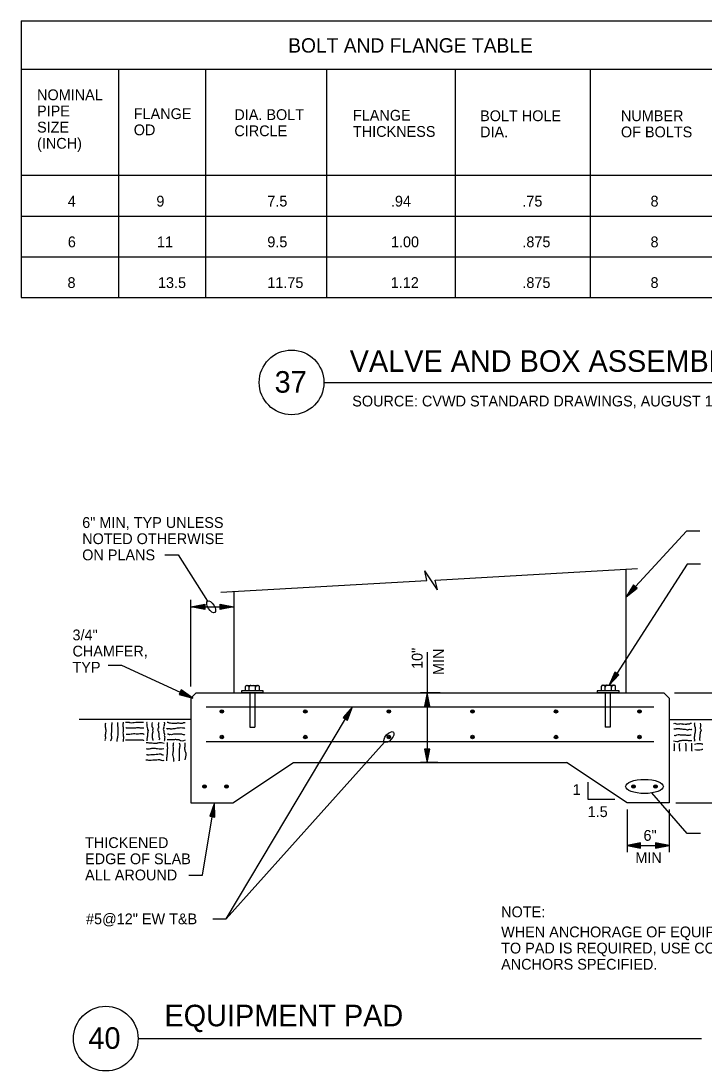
# Model space of a CAD drawing. Extents: x -121933 to -117742, y -103160 to -100084.
# Drawn here: x -121933 to -121553, y -102523 to -101938 of the extents above; entities that cross this region are included whole.
import ezdxf

# ---------------------------------------------------------------- set-up
doc = ezdxf.new("R2010")
doc.units = 0
for name, color, linetype in [('G-MARK', 7, 'Continuous'), ('G-TEXT', 7, 'Continuous'), ('Misc CnstDet(22)', 7, 'Continuous')]:
    doc.layers.add(name, color=color, linetype=linetype)

msp = doc.modelspace()

# ---------------------------------------------------------------- linework, layer by layer
at = {"layer": 'G-MARK'}
for p, q in [((-121814.85, -102255.67), (-121814.85, -102312.1)), ((-121838.79, -102308.56), (-121838.79, -102260.32)), ((-121838.79, -102264.16), (-121814.85, -102264.16)), ((-121707.41, -102289.5), (-121707.41, -102312.1)), ((-121707.41, -102312.1), (-121707.41, -102350.84)), ((-121569.78, -102312.1), (-121533.12, -102312.1)), ((-121569.05, -102373.35), (-121534.56, -102373.35)), ((-121596.02, -102397.06), (-121572.78, -102397.06))]:
    msp.add_line(p, q, dxfattribs=at)
for points in [[(-121555.66, -102222.01), (-121563.1, -102222.01), (-121591.46, -102252.81)], [(-121853.39, -102235.19), (-121845.95, -102235.19), (-121829.53, -102261.05)], [(-121555.27, -102240.38), (-121562.71, -102240.38), (-121601.87, -102301.24)], [(-121884.84, -102296.67), (-121877.4, -102296.67), (-121844.85, -102311.7)], [(-121826.61, -102437.78), (-121819.17, -102437.78), (-121752.89, -102326.51)], [(-121826.61, -102437.78), (-121819.17, -102437.78), (-121731.12, -102339.42)], [(-121603.03, -102371.42), (-121617.7, -102371.42), (-121617.7, -102361.72)], [(-121555.27, -102390.27), (-121562.71, -102390.27), (-121582.26, -102367.75)], [(-121839.9, -102413.63), (-121832.46, -102413.63), (-121826.94, -102380.99)]]:
    msp.add_lwpolyline(points, dxfattribs=at)
msp.add_ellipse((-121586.43, -102364.15), major_axis=(-10.49, 0), ratio=0.373805, dxfattribs=at)
at = {"layer": 'G-TEXT'}
for points in [[(-121590.45, -102253.74), (-121592.46, -102251.89), (-121596.71, -102258.52), (-121590.45, -102253.74), (-121591.71, -102253.09), (-121592.36, -102252.33), (-121595.53, -102257.33), (-121590.81, -102253.75), (-121591.88, -102253.27), (-121592.33, -102252.85), (-121594.56, -102256.28), (-121591.42, -102253.87), (-121592.32, -102253.11), (-121593.64, -102255.19), (-121591.86, -102253.8), (-121592.39, -102253.56), (-121592.8, -102254.27), (-121591.46, -102252.81)], [(-121831.1, -102262.74), (-121831.1, -102265.59), (-121838.79, -102264.16), (-121831.1, -102262.74), (-121831.48, -102264.16), (-121831.35, -102265.16), (-121837.06, -102264.1), (-121831.35, -102263.05), (-121831.72, -102264.16), (-121831.72, -102264.78), (-121835.69, -102264.1), (-121831.85, -102263.42), (-121831.91, -102264.6), (-121834.27, -102264.16), (-121832.1, -102263.79), (-121832.28, -102264.35), (-121833.03, -102264.16), (-121831.1, -102264.16)], [(-121822.54, -102265.59), (-121822.54, -102262.74), (-121814.85, -102264.16), (-121822.54, -102265.59), (-121822.17, -102264.16), (-121822.3, -102263.17), (-121816.59, -102264.23), (-121822.3, -102265.28), (-121821.92, -102264.16), (-121821.92, -102263.54), (-121817.96, -102264.23), (-121821.8, -102264.91), (-121821.74, -102263.73), (-121819.38, -102264.16), (-121821.55, -102264.54), (-121821.37, -102263.98), (-121820.62, -102264.16), (-121822.54, -102264.16)], [(-121600.72, -102301.98), (-121603.01, -102300.5), (-121606.06, -102307.76), (-121600.72, -102301.98), (-121602.07, -102301.55), (-121602.84, -102300.91), (-121605.1, -102306.38), (-121601.06, -102302.05), (-121602.2, -102301.76), (-121602.72, -102301.42), (-121604.33, -102305.18), (-121601.64, -102302.27), (-121602.67, -102301.68), (-121603.61, -102303.95), (-121602.09, -102302.27), (-121602.66, -102302.13), (-121602.94, -102302.91), (-121601.87, -102301.24)], [(-121844.28, -102310.46), (-121845.42, -102312.94), (-121837.81, -102314.95), (-121844.28, -102310.46), (-121844.51, -102311.86), (-121845.04, -102312.71), (-121839.31, -102314.2), (-121844.16, -102310.79), (-121844.29, -102311.96), (-121844.55, -102312.53), (-121840.6, -102313.6), (-121843.86, -102311.34), (-121844.3, -102312.44), (-121841.92, -102313.06), (-121843.79, -102311.78), (-121843.86, -102312.37), (-121843.05, -102312.54), (-121844.85, -102311.71)], [(-121708.89, -102319.54), (-121705.92, -102319.54), (-121707.41, -102312.1), (-121708.89, -102319.54), (-121707.41, -102319.18), (-121706.32, -102319.3), (-121707.47, -102313.71), (-121708.62, -102319.3), (-121707.41, -102318.94), (-121706.73, -102318.94), (-121707.47, -102315.07), (-121708.22, -102318.82), (-121706.93, -102318.77), (-121707.41, -102316.44), (-121707.81, -102318.59), (-121707.2, -102318.41), (-121707.41, -102317.63), (-121707.41, -102319.54)], [(-121754.06, -102325.81), (-121751.71, -102327.2), (-121748.92, -102319.85), (-121754.06, -102325.81), (-121752.69, -102326.19), (-121751.91, -102326.8), (-121749.83, -102321.25), (-121753.72, -102325.72), (-121752.57, -102325.97), (-121752.04, -102326.29), (-121750.56, -102322.48), (-121753.14, -102325.49), (-121752.1, -102326.04), (-121751.23, -102323.74), (-121752.7, -102325.46), (-121752.12, -102325.59), (-121751.87, -102324.8), (-121752.89, -102326.51)], [(-121705.92, -102343.4), (-121708.89, -102343.4), (-121707.41, -102350.84), (-121705.92, -102343.4), (-121707.41, -102343.76), (-121708.49, -102343.64), (-121707.34, -102349.23), (-121706.19, -102343.64), (-121707.41, -102344), (-121708.08, -102344), (-121707.34, -102347.86), (-121706.59, -102344.11), (-121707.88, -102344.17), (-121707.41, -102346.5), (-121707, -102344.35), (-121707.61, -102344.53), (-121707.41, -102345.31), (-121707.41, -102343.4)], [(-121828.28, -102380.76), (-121825.59, -102381.22), (-121825.65, -102373.35), (-121828.28, -102380.76), (-121826.88, -102380.62), (-121825.92, -102380.91), (-121825.98, -102374.99), (-121828, -102380.56), (-121826.83, -102380.38), (-121826.22, -102380.48), (-121826.22, -102376.39), (-121827.55, -102380.13), (-121826.38, -102380.27), (-121826.4, -102377.81), (-121827.14, -102379.95), (-121826.56, -102379.86), (-121826.61, -102379.03), (-121826.94, -102380.99)], [(-121588.59, -102398.56), (-121588.59, -102395.58), (-121596.03, -102397.07), (-121588.59, -102398.56), (-121588.94, -102397.07), (-121588.82, -102395.99), (-121594.42, -102397.13), (-121588.82, -102398.28), (-121589.18, -102397.07), (-121589.18, -102396.39), (-121593.05, -102397.13), (-121589.3, -102397.88), (-121589.36, -102396.59), (-121591.68, -102397.07), (-121589.54, -102397.47), (-121589.72, -102396.86), (-121590.49, -102397.07), (-121588.59, -102397.07)], [(-121580.22, -102395.58), (-121580.22, -102398.56), (-121572.78, -102397.07), (-121580.22, -102395.58), (-121579.87, -102397.07), (-121579.98, -102398.15), (-121574.39, -102397), (-121579.98, -102395.85), (-121579.63, -102397.07), (-121579.63, -102397.74), (-121575.76, -102397), (-121579.51, -102396.26), (-121579.45, -102397.54), (-121577.13, -102397.07), (-121579.27, -102396.66), (-121579.09, -102397.27), (-121578.32, -102397.07), (-121580.22, -102397.07)]]:
    msp.add_lwpolyline(points, dxfattribs=at)
for centre, major_axis in [((-121827.56, -102264.17), (1.99, -3.14)), ((-121728.65, -102336.68), (2.48, 2.77))]:
    msp.add_ellipse(centre, major_axis=major_axis, ratio=0.483333, dxfattribs=at)
at = {"layer": 'Misc CnstDet(22)'}
for p, q in [((-121933.35, -101938.08), (-121933.35, -102091.98)), ((-121933.35, -101938.08), (-121476.56, -101938.08)), ((-121933.35, -101964.93), (-121476.56, -101964.93)), ((-121879.09, -101964.93), (-121879.09, -102091.98)), ((-121830.78, -101964.93), (-121830.78, -102091.98)), ((-121763.4, -101964.93), (-121763.4, -102091.98)), ((-121691.84, -101964.93), (-121691.84, -102091.98)), ((-121616.7, -101964.93), (-121616.7, -102091.98)), ((-121933.35, -102023.98), (-121476.56, -102023.98)), ((-121933.35, -102046.65), (-121476.56, -102046.65)), ((-121933.35, -102069.32), (-121476.56, -102069.32)), ((-121933.35, -102091.98), (-121476.56, -102091.98)), ((-121764.82, -102139.26), (-121443.02, -102139.26)), ((-121707.58, -102249.59), (-121708.7, -102244.2)), ((-121701.69, -102254.74), (-121708.7, -102244.2)), ((-121702.99, -102249.28), (-121590.32, -102242.89)), ((-121596.71, -102312.1), (-121596.71, -102243.27)), ((-121822.11, -102256.04), (-121707.58, -102249.59)), ((-121707.58, -102249.59), (-121707.58, -102249.59)), ((-121701.69, -102254.74), (-121702.99, -102249.34)), ((-121702.99, -102249.34), (-121702.99, -102249.34)), ((-121814.85, -102264.16), (-121814.85, -102264.16)), ((-121808.41, -102310.98), (-121808.41, -102308.5)), ((-121807.79, -102307.88), (-121801.46, -102307.88)), ((-121806.42, -102310.98), (-121806.42, -102308.87)), ((-121802.83, -102310.98), (-121802.83, -102308.87)), ((-121800.72, -102310.98), (-121800.72, -102308.5)), ((-121610.29, -102310.86), (-121610.29, -102308.38)), ((-121609.67, -102307.76), (-121603.34, -102307.76)), ((-121608.3, -102310.86), (-121608.3, -102308.75)), ((-121604.71, -102310.86), (-121604.71, -102308.75)), ((-121602.6, -102310.86), (-121602.6, -102308.38)), ((-121838.79, -102315), (-121835.89, -102312.1)), ((-121838.79, -102315), (-121838.79, -102373.35)), ((-121835.89, -102312.1), (-121575.68, -102312.1)), ((-121806.08, -102311.91), (-121806.08, -102331.1)), ((-121803.17, -102311.91), (-121803.17, -102331.1)), ((-121700.05, -102312.1), (-121711.13, -102312.1)), ((-121608.4, -102311.91), (-121608.4, -102331.1)), ((-121605.49, -102311.91), (-121605.49, -102331.1)), ((-121575.68, -102312.1), (-121572.77, -102315)), ((-121572.77, -102315), (-121572.77, -102373.35)), ((-121830.36, -102319.85), (-121581.21, -102319.85)), ((-121838.79, -102326.86), (-121900.99, -102326.86)), ((-121572.77, -102326.86), (-121482.92, -102326.86)), ((-121806.08, -102331.1), (-121803.17, -102331.1)), ((-121605.49, -102331.1), (-121608.4, -102331.1)), ((-121830.36, -102339.22), (-121581.21, -102339.22)), ((-121815.55, -102373.35), (-121781.79, -102350.84)), ((-121781.79, -102350.84), (-121629.78, -102350.84)), ((-121701.44, -102350.84), (-121711.13, -102350.84)), ((-121596.02, -102373.35), (-121629.78, -102350.84)), ((-121838.79, -102373.35), (-121815.55, -102373.35)), ((-121572.77, -102373.35), (-121596.02, -102373.35)), ((-121596.02, -102377.07), (-121596.02, -102400.79)), ((-121572.78, -102377.07), (-121572.78, -102400.79)), ((-121868.18, -102504.54), (-121554.73, -102504.54))]:
    msp.add_line(p, q, dxfattribs=at)
for points in [[(-121810.7, -102311.91), (-121798.55, -102311.91), (-121798.55, -102310.98), (-121810.7, -102310.98)], [(-121612.71, -102311.91), (-121600.55, -102311.91), (-121600.55, -102310.98), (-121612.71, -102310.98)]]:
    msp.add_lwpolyline(points, close=True, dxfattribs=at)
for centre, radius in [((-121782.82, -102139.26), 18), ((-121821.64, -102322.39), 0.969), ((-121821.64, -102322.39), 0.581), ((-121821.64, -102322.39), 0.176), ((-121775.15, -102322.39), 0.969), ((-121775.15, -102322.39), 0.581), ((-121775.15, -102322.39), 0.176), ((-121728.66, -102322.39), 0.969), ((-121728.66, -102322.39), 0.581), ((-121728.66, -102322.39), 0.176), ((-121682.17, -102322.39), 0.969), ((-121682.17, -102322.39), 0.581), ((-121682.17, -102322.39), 0.176), ((-121635.68, -102322.39), 0.969), ((-121635.68, -102322.39), 0.581), ((-121635.68, -102322.39), 0.176), ((-121589.18, -102322.39), 0.969), ((-121589.18, -102322.39), 0.581), ((-121589.18, -102322.39), 0.176), ((-121821.64, -102336.67), 0.969), ((-121821.64, -102336.67), 0.581), ((-121821.64, -102336.67), 0.176), ((-121775.15, -102336.67), 0.969), ((-121775.15, -102336.67), 0.581), ((-121775.15, -102336.67), 0.176), ((-121728.66, -102336.67), 0.969), ((-121728.66, -102336.67), 0.581), ((-121728.66, -102336.67), 0.176), ((-121682.17, -102336.67), 0.969), ((-121682.17, -102336.67), 0.581), ((-121682.17, -102336.67), 0.176), ((-121635.68, -102336.67), 0.969), ((-121635.68, -102336.67), 0.581), ((-121635.68, -102336.67), 0.176), ((-121589.18, -102336.67), 0.969), ((-121589.18, -102336.67), 0.581), ((-121589.18, -102336.67), 0.176), ((-121831.25, -102364.18), 0.969), ((-121831.25, -102364.18), 0.581), ((-121831.25, -102364.18), 0.176), ((-121819.02, -102364.18), 0.969), ((-121819.02, -102364.18), 0.581), ((-121819.02, -102364.18), 0.176), ((-121592.54, -102364.18), 0.969), ((-121592.54, -102364.18), 0.581), ((-121592.54, -102364.18), 0.176), ((-121580.32, -102364.18), 0.969), ((-121580.32, -102364.18), 0.581), ((-121580.32, -102364.18), 0.176), ((-121886.18, -102504.54), 18)]:
    msp.add_circle(centre, radius, dxfattribs=at)
for centre, radius, start, end in [((-121807.81, -102308.56), 0.674, 90.00002, 180.00002), ((-121807.41, -102308.93), 1.01, 359.99997, 89.99997), ((-121805.39, -102308.93), 1.01, 90.00003, 180.00003), ((-121803.84, -102308.93), 1.01, 359.99997, 89.99997), ((-121801.81, -102308.93), 1.01, 90.00003, 180.00003), ((-121801.41, -102308.56), 0.674, 0.00002, 90.00002), ((-121609.69, -102308.43), 0.674, 90.00002, 180.00002), ((-121609.29, -102308.8), 1.01, 359.99997, 89.99997), ((-121607.27, -102308.8), 1.01, 90.00003, 180.00003), ((-121605.72, -102308.8), 1.01, 359.99997, 89.99997), ((-121603.7, -102308.8), 1.01, 90.00003, 180.00003), ((-121603.29, -102308.43), 0.674, 0.00002, 90.00002)]:
    msp.add_arc(centre, radius, start, end, dxfattribs=at)
for points in [[(-121886.41, -102328.84), (-121886.41, -102331.57), (-121886.23, -102332.62), (-121886.35, -102334.3), (-121886.41, -102336.71), (-121886.41, -102337.46), (-121886.6, -102337.83), (-121886.6, -102338.57)], [(-121882.75, -102328.53), (-121882.94, -102330.58), (-121883, -102333.06), (-121883.19, -102334.61), (-121883.19, -102335.85), (-121883.19, -102338.02), (-121883.44, -102338.82), (-121883.37, -102338.82)], [(-121879.65, -102328.53), (-121879.59, -102330.64), (-121879.47, -102331.2), (-121879.47, -102333.61), (-121879.59, -102336.28), (-121879.65, -102336.96), (-121880.09, -102338.64), (-121880.09, -102339.07)], [(-121876.55, -102328.34), (-121876.62, -102330.64), (-121876.55, -102333.06), (-121876.62, -102334.23), (-121876.43, -102335.91), (-121876.37, -102337.33), (-121876.55, -102338.7), (-121876.62, -102339.13)], [(-121865.21, -102328.65), (-121869.55, -102328.65), (-121871.22, -102328.78), (-121872.59, -102328.78), (-121872.96, -102328.65), (-121875.13, -102328.53)], [(-121864.96, -102331.63), (-121866.57, -102331.75), (-121867.5, -102331.57), (-121868.37, -102331.57), (-121870.97, -102331.69), (-121873.58, -102331.69), (-121874.57, -102331.63), (-121875.07, -102331.38)], [(-121863.16, -102328.65), (-121863.29, -102328.65), (-121863.41, -102329.4), (-121863.41, -102330.64), (-121863.04, -102332.13), (-121863.04, -102332.37), (-121862.91, -102332.5), (-121862.91, -102334.73), (-121862.91, -102335.23), (-121863.04, -102335.47), (-121863.04, -102336.34), (-121863.16, -102336.47), (-121863.16, -102337.02), (-121863.29, -102337.52), (-121863.29, -102338.26), (-121863.41, -102338.39), (-121863.29, -102338.51), (-121863.29, -102338.76)], [(-121860.31, -102328.65), (-121860.31, -102331.13), (-121860.18, -102331.26), (-121860.06, -102333.49), (-121860.06, -102333.86), (-121860.18, -102333.86), (-121860.18, -102334.61), (-121860.31, -102334.73), (-121860.31, -102335.97), (-121860.31, -102337.15), (-121860.18, -102337.27), (-121860.18, -102338.02), (-121860.06, -102338.02), (-121860.06, -102338.26), (-121859.94, -102338.64)], [(-121856.84, -102328.65), (-121856.84, -102331.26), (-121856.84, -102331.63), (-121856.96, -102331.75), (-121856.96, -102333.37), (-121856.84, -102333.49), (-121856.84, -102334.11), (-121856.59, -102334.98), (-121856.59, -102336.47), (-121856.59, -102338.14), (-121856.71, -102338.26), (-121856.59, -102338.26)], [(-121853.67, -102328.41), (-121853.55, -102328.78), (-121853.55, -102329.4), (-121853.67, -102329.52), (-121853.67, -102330.39), (-121853.8, -102330.51), (-121853.92, -102331.51), (-121853.92, -102331.75), (-121854.04, -102331.88), (-121854.04, -102332.87), (-121853.92, -102333.12), (-121853.92, -102333.86), (-121853.8, -102334.11), (-121853.8, -102334.48), (-121853.67, -102334.61), (-121853.55, -102336.09), (-121853.42, -102336.22), (-121853.42, -102337.15), (-121853.42, -102337.27), (-121853.55, -102337.52), (-121853.55, -102338.39), (-121853.67, -102338.64), (-121853.55, -102338.64), (-121853.55, -102338.51)], [(-121842.2, -102331.88), (-121842.45, -102331.75), (-121843.19, -102331.75), (-121843.57, -102331.63), (-121845.18, -102331.63), (-121845.8, -102331.75), (-121846.54, -102331.75), (-121847.84, -102332), (-121848.46, -102332), (-121849.46, -102332.25), (-121850.08, -102332.25), (-121850.32, -102332.13), (-121851.81, -102332.13), (-121851.69, -102332.13), (-121852.18, -102332), (-121852.18, -102331.88), (-121852.18, -102332)], [(-121842.08, -102328.72), (-121843.07, -102328.78), (-121843.69, -102329.03), (-121844.81, -102329.03), (-121846.91, -102329.03), (-121847.29, -102329.15), (-121847.84, -102329.03), (-121849.08, -102329.15), (-121849.46, -102329.03), (-121850.94, -102328.9), (-121851.44, -102328.65), (-121851.94, -102328.65)], [(-121570.13, -102329.03), (-121569.14, -102329.09), (-121568.52, -102329.34), (-121567.4, -102329.34), (-121565.29, -102329.34), (-121564.92, -102329.46), (-121564.36, -102329.34), (-121563.12, -102329.46), (-121562.75, -102329.34), (-121561.26, -102329.21), (-121560.77, -102328.96), (-121560.27, -102328.96)], [(-121570, -102332.19), (-121569.76, -102332.06), (-121569.01, -102332.06), (-121568.64, -102331.94), (-121567.03, -102331.94), (-121566.41, -102332.06), (-121565.66, -102332.06), (-121564.36, -102332.31), (-121563.74, -102332.31), (-121562.75, -102332.56), (-121562.13, -102332.56), (-121561.88, -102332.44), (-121560.39, -102332.44), (-121560.52, -102332.44), (-121560.02, -102332.31), (-121560.02, -102332.19), (-121560.02, -102332.31)], [(-121558.53, -102328.72), (-121558.66, -102329.09), (-121558.66, -102329.71), (-121558.53, -102329.83), (-121558.53, -102330.7), (-121558.41, -102330.82), (-121558.29, -102331.82), (-121558.29, -102332.06), (-121558.16, -102332.19), (-121558.16, -102333.18), (-121558.29, -102333.43), (-121558.29, -102334.17), (-121558.41, -102334.42), (-121558.41, -102334.79), (-121558.53, -102334.92), (-121558.66, -102336.4), (-121558.78, -102336.53), (-121558.78, -102337.46), (-121558.78, -102337.58), (-121558.66, -102337.83), (-121558.66, -102338.7), (-121558.53, -102338.95), (-121558.66, -102338.95), (-121558.66, -102338.82)], [(-121555.37, -102328.96), (-121555.37, -102331.57), (-121555.37, -102331.94), (-121555.25, -102332.06), (-121555.25, -102333.68), (-121555.37, -102333.8), (-121555.37, -102334.42), (-121555.62, -102335.29), (-121555.62, -102336.78), (-121555.62, -102338.45), (-121555.49, -102338.57), (-121555.62, -102338.57)], [(-121864.96, -102338.7), (-121865.21, -102338.57), (-121867.01, -102338.39), (-121869.73, -102338.39), (-121872.52, -102338.39), (-121875.13, -102338.33)], [(-121864.9, -102335.16), (-121865.15, -102335.04), (-121866.01, -102334.92), (-121868.56, -102334.98), (-121871.47, -102334.98), (-121873.95, -102335.23), (-121874.69, -102335.16), (-121874.88, -102335.16)], [(-121841.95, -102338.39), (-121845.18, -102338.39), (-121845.3, -102338.26), (-121845.92, -102338.26), (-121846.42, -102338.26), (-121847.16, -102338.02), (-121847.97, -102338.14), (-121849.58, -102338.14), (-121850.57, -102338.26), (-121852.06, -102338.26)], [(-121842.2, -102335.23), (-121842.33, -102335.35), (-121843.81, -102335.1), (-121846.29, -102335.1), (-121848.59, -102335.1), (-121849.58, -102335.35), (-121850.7, -102335.35), (-121850.94, -102335.35), (-121850.94, -102335.23), (-121850.94, -102335.35), (-121850.94, -102335.23), (-121851.19, -102335.23), (-121851.32, -102335.1), (-121851.81, -102335.1)], [(-121570.25, -102338.7), (-121567.03, -102338.7), (-121566.9, -102338.57), (-121566.28, -102338.57), (-121565.79, -102338.57), (-121565.04, -102338.33), (-121564.24, -102338.45), (-121562.63, -102338.45), (-121561.63, -102338.57), (-121560.15, -102338.57)], [(-121570, -102335.54), (-121569.88, -102335.66), (-121568.39, -102335.41), (-121565.91, -102335.41), (-121563.62, -102335.41), (-121562.63, -102335.66), (-121561.51, -102335.66), (-121561.26, -102335.66), (-121561.26, -102335.54), (-121561.26, -102335.66), (-121561.26, -102335.54), (-121561.01, -102335.54), (-121560.89, -102335.41), (-121560.39, -102335.41)], [(-121853.61, -102340.25), (-121856.71, -102339.94), (-121857.58, -102340.12), (-121858.14, -102340.25), (-121861.24, -102340.06), (-121862.11, -102340.06), (-121863.22, -102339.88), (-121863.35, -102339.94), (-121863.72, -102339.88)], [(-121853.8, -102343.29), (-121857.46, -102343.29), (-121857.89, -102343.16), (-121860.68, -102343.1), (-121861.55, -102343.29), (-121863.47, -102343.22), (-121863.53, -102343.16)], [(-121851.94, -102339.69), (-121851.94, -102341.86), (-121851.94, -102343.53), (-121852.06, -102343.97), (-121852.06, -102344.77), (-121852.06, -102346.2), (-121852.25, -102347.13), (-121852.25, -102347.69), (-121852.49, -102348.68), (-121852.43, -102349.3), (-121852.31, -102349.92)], [(-121848.53, -102339.81), (-121848.71, -102340.56), (-121848.71, -102342.79), (-121848.71, -102344.46), (-121848.84, -102344.77), (-121848.96, -102345.89), (-121849.02, -102346.64), (-121848.84, -102347.19), (-121848.59, -102348.68), (-121848.4, -102349.61), (-121848.46, -102350.23)], [(-121845.3, -102339.88), (-121844.99, -102341.05), (-121845.12, -102342.29), (-121845.3, -102343.35), (-121845.3, -102345.27), (-121845.3, -102347.57), (-121845.3, -102349.49), (-121845.3, -102349.74), (-121845.36, -102349.86), (-121845.36, -102349.61)], [(-121842.26, -102339.94), (-121842.26, -102342.05), (-121842.33, -102343.22), (-121842.14, -102344.28), (-121841.71, -102345.7), (-121841.71, -102346.39), (-121841.71, -102347.13), (-121842.08, -102348.87), (-121842.14, -102349.36)], [(-121569.94, -102340.25), (-121569.94, -102342.36), (-121569.88, -102343.53), (-121570.07, -102344.53)], [(-121566.9, -102340.19), (-121567.21, -102341.36), (-121567.09, -102342.6), (-121566.9, -102343.66), (-121566.9, -102344.53)], [(-121563.68, -102340.12), (-121563.49, -102340.87), (-121563.49, -102343.1), (-121563.49, -102344.53)], [(-121560.27, -102340), (-121560.27, -102342.17), (-121560.27, -102343.84), (-121560.15, -102344.28), (-121560.15, -102344.53)], [(-121558.6, -102340.56), (-121555.49, -102340.25), (-121554.63, -102340.43), (-121554.07, -102340.56), (-121554.01, -102340.56)], [(-121558.41, -102343.6), (-121554.75, -102343.6), (-121554.32, -102343.47), (-121554.01, -102343.41)], [(-121853.8, -102349.8), (-121855.16, -102349.74), (-121855.35, -102349.61), (-121857.02, -102349.43), (-121858.63, -102349.61), (-121859.94, -102349.61), (-121861.73, -102349.74), (-121862.73, -102349.55), (-121863.84, -102349.49)], [(-121853.98, -102346.76), (-121854.73, -102346.64), (-121854.91, -102346.51), (-121858.14, -102346.45), (-121862.11, -102346.76), (-121862.79, -102346.76), (-121863.22, -102346.51), (-121863.47, -102346.51)]]:
    msp.add_spline(points, degree=3, dxfattribs=at)

# ---------------------------------------------------------------- texts
at = {"layer": 'G-MARK'}
for s, p in [('6" MIN, TYP UNLESS', (-121899.31, -102220.26)), ('NOTED OTHERWISE', (-121899.31, -102229.26)), ('ON PLANS', (-121899.31, -102238.26)), ('3/4"', (-121904.7, -102282.82)), ('CHAMFER,', (-121904.7, -102291.82)), ('TYP', (-121904.7, -102300.82))]:
    msp.add_text(s, height=6, dxfattribs=at).set_placement(p)
at = {"layer": 'Misc CnstDet(22)'}
for s, height, p in [('BOLT AND FLANGE TABLE', 8, (-121784.7, -101955.68)), ('NOMINAL', 6, (-121924.42, -101982.17)), ('PIPE', 6, (-121924.42, -101991.17)), ('FLANGE', 6, (-121870.62, -101992.67)), ('DIA. BOLT', 6, (-121814.64, -101993.21)), ('FLANGE', 6, (-121748.66, -101993.57)), ('BOLT HOLE', 6, (-121677.89, -101993.84)), ('NUMBER', 6, (-121599.54, -101993.84)), ('SIZE', 6, (-121924.42, -102000.17)), ('OD', 6, (-121870.62, -102001.67)), ('CIRCLE', 6, (-121814.64, -102002.21)), ('THICKNESS', 6, (-121748.66, -102002.57)), ('DIA.', 6, (-121677.89, -102002.84)), ('OF BOLTS', 6, (-121599.54, -102002.84)), ('(INCH)', 6, (-121924.42, -102009.17)), ('4', 6, (-121907.31, -102041.36)), ('9', 6, (-121858.03, -102041.36)), ('7.5', 6, (-121796.31, -102041.36)), ('.94', 6, (-121727.54, -102041.36)), ('.75', 6, (-121654.39, -102041.36)), ('8', 6, (-121583.08, -102041.36)), ('6', 6, (-121907.3, -102064.03)), ('11', 6, (-121857.73, -102064.03)), ('9.5', 6, (-121796.31, -102064.03)), ('1.00', 6, (-121727.51, -102064.03)), ('.875', 6, (-121654.38, -102064.03)), ('8', 6, (-121583.08, -102064.03)), ('8', 6, (-121907.48, -102086.7)), ('13.5', 6, (-121857.14, -102086.7)), ('11.75', 6, (-121796.31, -102086.7)), ('1.12', 6, (-121727.63, -102086.7)), ('.875', 6, (-121654.38, -102086.7)), ('8', 6, (-121583.08, -102086.7)), ('VALVE AND BOX ASSEMBLY', 12, (-121750.45, -102133.37)), ('37', 12, (-121792.23, -102144.98)), ('SOURCE: CVWD STANDARD DRAWINGS, AUGUST 15, 2005', 6, (-121749.04, -102152.64)), ('1', 6, (-121626.43, -102368.9)), ('1.5', 6, (-121618.07, -102381.21)), ('6"', 6, (-121586.99, -102394.41)), ('THICKENED', 6, (-121897.7, -102398.44)), ('EDGE OF SLAB', 6, (-121897.7, -102407.44)), ('MIN', 6, (-121591.52, -102406.76)), ('ALL AROUND', 6, (-121897.7, -102416.44)), ('NOTE:', 6, (-121666.2, -102436.97)), ('#5@12" EW T&B', 6, (-121897.16, -102440.87)), ('WHEN ANCHORAGE OF EQUIPMENT', 6, (-121666.2, -102448.13)), ('TO PAD IS REQUIRED, USE CONCRETE', 6, (-121666.2, -102457.13)), ('ANCHORS SPECIFIED.', 6, (-121666.2, -102466.13)), ('EQUIPMENT PAD', 12, (-121853.53, -102497.67)), ('40', 12, (-121895.84, -102510.21))]:
    msp.add_text(s, height=height, dxfattribs=at).set_placement(p)
for s, p in [('10"', (-121709.92, -102298.74)), ('MIN', (-121698.06, -102302.12))]:
    msp.add_text(s, height=6, rotation=90, dxfattribs=at).set_placement(p)

doc.saveas('drawing.dxf')
